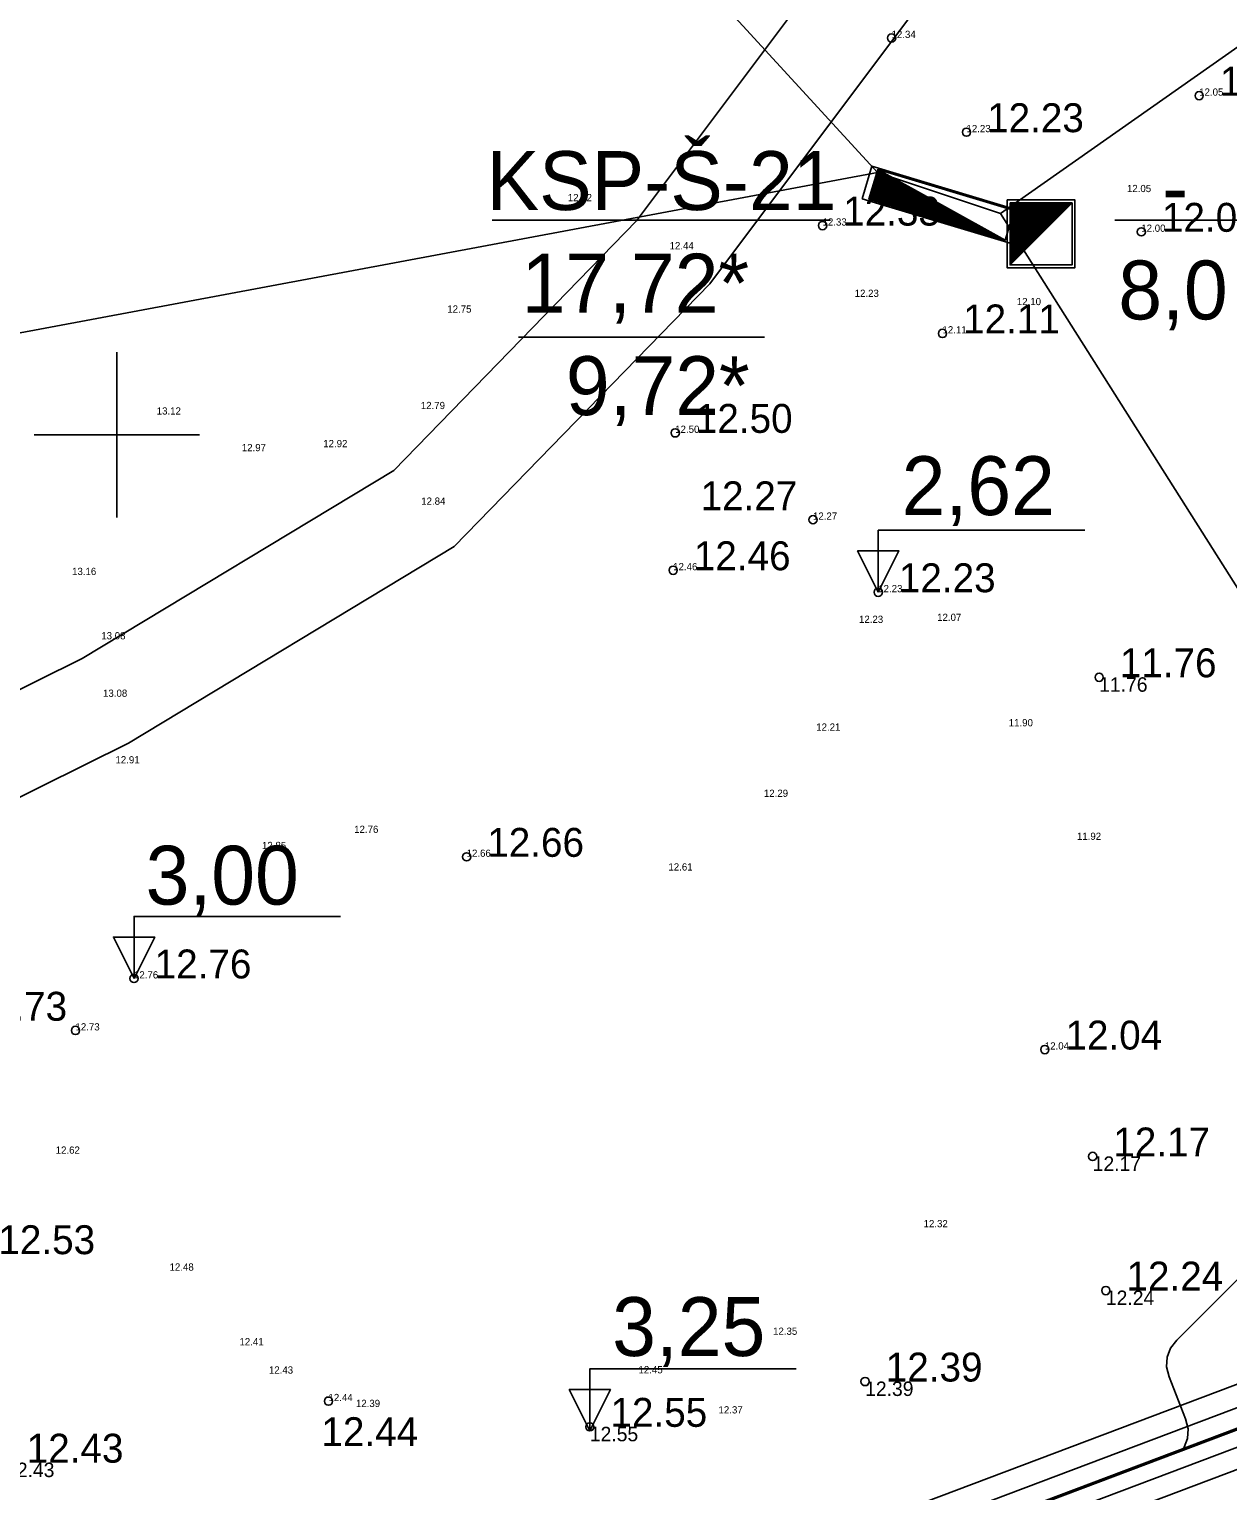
# Model space of a CAD drawing. Extents: x 433497 to 434382, y 6534486 to 6534993.
# Drawn here: x 433695.8 to 433753.8, y 6534648.9 to 6534719.6 of the extents above; entities that cross this region are included whole.
import ezdxf

# ---------------------------------------------------------------- set-up
doc = ezdxf.new("R2010")
doc.units = 0
for name, color, linetype in [('Default', 7, 'Continuous'), ('GEOLPUNKT', 7, 'Continuous'), ('jääkpaksus', 7, 'Continuous'), ('kataster', 7, 'Continuous'), ('KORGUS-EH2000', 7, 'Continuous'), ('l__x00e4__bil__x00f5__iked', 7, 'Continuous'), ('Lamami horisontaal', 7, 'Continuous'), ('MOOTKORG-EH2000', 7, 'Continuous'), ('PIIR', 7, 'Continuous'), ('TEE', 7, 'Continuous'), ('VORK', 7, 'Continuous')]:
    doc.layers.add(name, color=color, linetype=linetype)

msp = doc.modelspace()

# ---------------------------------------------------------------- linework, layer by layer
at = {"layer": 'Default'}
msp.add_lwpolyline([(433617.12, 6534791.025), (433632.75, 6534606.045), (434137.38, 6534796.515), (434127.69, 6534855.6), (433968.21, 6534911.925), (433942.38, 6534904.035), (433920.99, 6534907.275)], close=True, dxfattribs=at)
msp.add_lwpolyline([(433617.12, 6534791.025), (433632.75, 6534606.045), (434137.38, 6534796.515), (434127.69, 6534855.6), (433968.21, 6534911.925), (433942.38, 6534904.035), (433920.99, 6534907.275)], close=True, dxfattribs=at)
msp.add_lwpolyline([(433617.12, 6534791.025), (433632.75, 6534606.045), (434137.38, 6534796.515), (434127.69, 6534855.6), (433968.21, 6534911.925), (433942.38, 6534904.035), (433920.99, 6534907.275)], close=True, dxfattribs=at)
at = {"layer": 'GEOLPUNKT'}
for p, q in [((433742.498, 6534709.584), (433736.822, 6534712.731)), ((433742.654, 6534709.537), (433736.832, 6534712.765)), ((433742.809, 6534709.491), (433736.842, 6534712.799)), ((433742.965, 6534709.444), (433736.852, 6534712.833)), ((433743.032, 6534709.424), (433736.857, 6534712.847)), ((433739.227, 6534710.568), (433736.608, 6534712.02)), ((433739.383, 6534710.521), (433736.618, 6534712.054)), ((433739.539, 6534710.474), (433736.628, 6534712.088)), ((433739.695, 6534710.427), (433736.639, 6534712.122)), ((433739.85, 6534710.381), (433736.649, 6534712.156)), ((433740.006, 6534710.334), (433736.659, 6534712.19)), ((433740.162, 6534710.287), (433736.669, 6534712.223)), ((433740.318, 6534710.24), (433736.679, 6534712.257)), ((433740.473, 6534710.193), (433736.69, 6534712.291)), ((433740.629, 6534710.146), (433736.7, 6534712.325)), ((433740.785, 6534710.1), (433736.71, 6534712.359)), ((433740.941, 6534710.053), (433736.72, 6534712.393)), ((433741.096, 6534710.006), (433736.73, 6534712.427)), ((433741.252, 6534709.959), (433736.74, 6534712.46)), ((433741.408, 6534709.912), (433736.751, 6534712.494)), ((433741.564, 6534709.865), (433736.761, 6534712.528)), ((433741.719, 6534709.818), (433736.771, 6534712.562)), ((433741.875, 6534709.772), (433736.781, 6534712.596)), ((433742.031, 6534709.725), (433736.791, 6534712.63)), ((433742.187, 6534709.678), (433736.802, 6534712.664)), ((433742.342, 6534709.631), (433736.812, 6534712.697)), ((433736.58, 6534711.364), (433736.435, 6534711.445)), ((433736.736, 6534711.318), (433736.445, 6534711.479)), ((433736.891, 6534711.271), (433736.455, 6534711.512)), ((433737.047, 6534711.224), (433736.465, 6534711.546)), ((433737.203, 6534711.177), (433736.476, 6534711.58)), ((433737.359, 6534711.13), (433736.486, 6534711.614)), ((433737.514, 6534711.083), (433736.496, 6534711.648)), ((433737.67, 6534711.036), (433736.506, 6534711.682)), ((433737.826, 6534710.99), (433736.516, 6534711.716)), ((433737.982, 6534710.943), (433736.527, 6534711.749)), ((433738.137, 6534710.896), (433736.537, 6534711.783)), ((433738.293, 6534710.849), (433736.547, 6534711.817)), ((433738.449, 6534710.802), (433736.557, 6534711.851)), ((433738.604, 6534710.755), (433736.567, 6534711.885)), ((433738.76, 6534710.709), (433736.577, 6534711.919)), ((433738.916, 6534710.662), (433736.588, 6534711.953)), ((433739.072, 6534710.615), (433736.598, 6534711.986)), ((433743.262, 6534708.233), (433746.262, 6534711.233)), ((433743.262, 6534708.263), (433746.232, 6534711.233)), ((433743.262, 6534708.334), (433746.161, 6534711.233)), ((433743.262, 6534708.405), (433746.09, 6534711.233)), ((433743.262, 6534708.476), (433746.02, 6534711.233)), ((433743.262, 6534708.546), (433745.949, 6534711.233)), ((433743.262, 6534708.617), (433745.878, 6534711.233)), ((433743.262, 6534708.688), (433745.807, 6534711.233)), ((433743.262, 6534708.758), (433745.737, 6534711.233)), ((433743.262, 6534708.829), (433745.666, 6534711.233)), ((433743.262, 6534708.9), (433745.595, 6534711.233)), ((433743.262, 6534708.971), (433745.525, 6534711.233)), ((433743.262, 6534709.041), (433745.454, 6534711.233)), ((433743.262, 6534709.112), (433745.383, 6534711.233)), ((433743.262, 6534709.183), (433745.313, 6534711.233)), ((433743.262, 6534709.253), (433745.242, 6534711.233)), ((433743.262, 6534709.324), (433745.171, 6534711.233)), ((433743.262, 6534709.395), (433745.1, 6534711.233)), ((433743.262, 6534709.465), (433745.03, 6534711.233)), ((433743.262, 6534709.536), (433744.959, 6534711.233)), ((433743.262, 6534709.607), (433744.888, 6534711.233)), ((433743.262, 6534709.678), (433744.818, 6534711.233)), ((433743.262, 6534709.748), (433744.747, 6534711.233)), ((433743.262, 6534709.819), (433744.676, 6534711.233)), ((433743.262, 6534709.89), (433744.605, 6534711.233)), ((433743.262, 6534709.96), (433744.535, 6534711.233)), ((433743.262, 6534710.031), (433744.464, 6534711.233)), ((433743.262, 6534710.102), (433744.393, 6534711.233)), ((433743.262, 6534710.173), (433744.323, 6534711.233)), ((433743.262, 6534710.243), (433744.252, 6534711.233)), ((433743.262, 6534710.314), (433744.181, 6534711.233)), ((433743.262, 6534710.385), (433744.11, 6534711.233)), ((433743.262, 6534710.455), (433744.04, 6534711.233)), ((433743.262, 6534710.526), (433743.969, 6534711.233)), ((433743.262, 6534710.597), (433743.898, 6534711.233)), ((433743.262, 6534710.668), (433743.828, 6534711.233)), ((433743.262, 6534710.738), (433743.757, 6534711.233)), ((433743.262, 6534710.809), (433743.686, 6534711.233)), ((433743.262, 6534710.88), (433743.615, 6534711.233)), ((433743.262, 6534710.95), (433743.545, 6534711.233)), ((433743.262, 6534711.021), (433743.474, 6534711.233)), ((433743.262, 6534711.092), (433743.403, 6534711.233)), ((433743.262, 6534711.163), (433743.333, 6534711.233)), ((433744.762, 6534709.733), (433744.762, 6534709.733))]:
    msp.add_line(p, q, dxfattribs=at)
for points in [[(433736.094, 6534711.437), (433736.567, 6534713.008), (433743.795, 6534710.834), (433743.323, 6534709.263)], [(433736.425, 6534711.411), (433736.857, 6534712.847), (433743.464, 6534710.86), (433743.032, 6534709.424)], [(433743.121, 6534711.374), (433746.403, 6534711.374), (433746.403, 6534708.092), (433743.121, 6534708.092)], [(433743.262, 6534711.233), (433746.262, 6534711.233), (433746.262, 6534708.233), (433743.262, 6534708.233)]]:
    msp.add_lwpolyline(points, close=True, dxfattribs=at)
for points in [[(433718.185, 6534710.392), (433734.57, 6534710.392)], [(433748.334, 6534710.392), (433754.462, 6534710.392)], [(433719.456, 6534704.738), (433731.372, 6534704.738)]]:
    msp.add_lwpolyline(points, dxfattribs=at)
at = {"layer": 'jääkpaksus'}
for points in [[(433736.877, 6534692.381), (433736.877, 6534695.381), (433746.877, 6534695.381)], [(433700.832, 6534673.681), (433700.832, 6534676.681), (433710.832, 6534676.681)], [(433722.908, 6534651.771), (433722.908, 6534654.771), (433732.908, 6534654.771)]]:
    msp.add_lwpolyline(points, dxfattribs=at)
for points in [[(433736.877, 6534692.381), (433735.877, 6534694.381), (433737.877, 6534694.381)], [(433700.832, 6534673.681), (433699.832, 6534675.681), (433701.832, 6534675.681)], [(433722.908, 6534651.771), (433721.908, 6534653.771), (433723.908, 6534653.771)]]:
    msp.add_lwpolyline(points, close=True, dxfattribs=at)
at = {"layer": 'kataster'}
msp.add_lwpolyline([(433617.102, 6534791.002), (433632.769, 6534606.029), (434137.446, 6534796.469), (434127.827, 6534855.589), (433950.026, 6534918.39)], close=True, dxfattribs=at)
at = {"layer": 'KORGUS-EH2000'}
for centre in [(433737.522, 6534719.218), (433752.422, 6534716.424), (433741.151, 6534714.657), (433734.18, 6534710.135), (433749.618, 6534709.833), (433739.989, 6534704.913), (433727.044, 6534700.098), (433733.718, 6534695.893), (433726.946, 6534693.446), (433736.877, 6534692.381), (433747.578, 6534688.263), (433716.941, 6534679.57), (433700.832, 6534673.681), (433697.997, 6534671.163), (433744.945, 6534670.239), (433747.263, 6534665.062), (433747.902, 6534658.569), (433736.242, 6534654.164), (433710.252, 6534653.215), (433722.908, 6534651.971)]:
    msp.add_circle(centre, 0.2, dxfattribs=at)
at = {"layer": 'l__x00e4__bil__x00f5__iked'}
for points in [[(433620.07, 6534691.039), (433627.105, 6534692.187), (433736.834, 6534712.709), (433742.792, 6534710.723), (433822.234, 6534766.498), (433986.579, 6534812.177), (434120.472, 6534848.091), (434132.163, 6534850.175)], [(433633.89, 6534824.093), (433654.744, 6534802.081), (433736.834, 6534712.709), (433742.792, 6534710.723), (433773.907, 6534661.568), (433785.989, 6534638.563)]]:
    msp.add_lwpolyline(points, dxfattribs=at)
at = {"layer": 'Lamami horisontaal'}
msp.add_lwpolyline([(433751.537, 6534650.808), (433751.689, 6534650.989), (433751.864, 6534651.411), (433751.889, 6534651.867), (433751.765, 6534652.358), (433750.971, 6534654.387), (433750.846, 6534654.88), (433750.866, 6534655.341), (433751.032, 6534655.772), (433751.344, 6534656.173), (433763.457, 6534668.298)], dxfattribs=at)
at = {"layer": 'PIIR'}
for points in [[(433632.021, 6534604.835), (434138.248, 6534795.936), (434128.468, 6534856.135), (433968.226, 6534912.818), (433942.33, 6534904.85), (433920.952, 6534908.165), (433616.327, 6534791.524), (433632.021, 6534604.835)], [(433632.732, 6534605.959), (434137.353, 6534796.454), (434127.754, 6534855.539), (433968.208, 6534911.976), (433942.39, 6534904.031), (433921.04, 6534907.341), (433617.174, 6534790.992), (433632.732, 6534605.959)], [(433633.446, 6534604.304), (434134.891, 6534793.6)]]:
    msp.add_lwpolyline(points, dxfattribs=at)
for points in [[(433618.234, 6534790.327), (433921.149, 6534906.313), (433942.464, 6534903.008), (433968.187, 6534910.923), (434126.862, 6534854.794), (434136.235, 6534797.101), (433633.617, 6534607.362)], [(433619.24, 6534789.695), (433634.52, 6534608.851), (434135.141, 6534797.808), (434125.908, 6534854.108), (433968.165, 6534909.82), (433942.53, 6534901.99), (433921.212, 6534905.219)], [(433619.24, 6534789.695), (433634.52, 6534608.851), (434135.141, 6534797.808), (434125.908, 6534854.108), (433968.165, 6534909.82), (433942.53, 6534901.99), (433921.212, 6534905.219)]]:
    msp.add_lwpolyline(points, close=True, dxfattribs=at)
at = {"layer": 'TEE'}
for points in [[(433629.62, 6534620.933), (433635.717, 6534625.88), (433648.001, 6534643.205), (433657.255, 6534659.779), (433669.771, 6534672.932), (433683.244, 6534681.694), (433698.319, 6534689.166), (433713.422, 6534698.28), (433725.167, 6534710.357), (433749.242, 6534742.46), (433772.059, 6534766.624), (433790.138, 6534781.288), (433800.698, 6534786.54), (433824.398, 6534799.304), (433830.425, 6534802.129), (433845.699, 6534809.155)], [(433604.844, 6534600.897), (433614.152, 6534605.53), (433628.909, 6534614.355), (433639.149, 6534622.663), (433651.948, 6534640.714), (433661.037, 6534656.993), (433672.77, 6534669.323), (433685.557, 6534677.639), (433700.561, 6534685.076), (433716.344, 6534694.6), (433728.716, 6534707.321), (433752.812, 6534739.453), (433775.036, 6534762.988), (433798.049, 6534780.902), (433815.08, 6534789.81), (433832.403, 6534797.909), (433848.041, 6534804.286)]]:
    msp.add_lwpolyline(points, dxfattribs=at)
at = {"layer": 'VORK'}
for p, q in [((433700, 6534704), (433700, 6534696)), ((433696, 6534700), (433704, 6534700))]:
    msp.add_line(p, q, dxfattribs=at)

# ---------------------------------------------------------------- texts
at = {"layer": 'GEOLPUNKT'}
for s, p in [('KSP-Š-21', (433717.911, 6534710.888)), ('-', (433750.624, 6534710.557)), ('17,72*', (433719.603, 6534705.923)), ('8,0', (433748.505, 6534705.592)), ('9,72*', (433721.748, 6534700.958))]:
    msp.add_text(s, height=2.85, dxfattribs=at).set_placement(p)
at = {"layer": 'jääkpaksus'}
for s, p in [('2,62', (433738.013, 6534696.116)), ('3,00', (433701.395, 6534677.256)), ('3,25', (433723.99, 6534655.399))]:
    msp.add_text(s, height=2.85, rotation=360, dxfattribs=at).set_placement(p)
at = {"layer": 'KORGUS-EH2000'}
for s, p in [('12.05', (433753.422, 6534716.424)), ('12.23', (433742.151, 6534714.657)), ('12.33', (433735.18, 6534710.135)), ('12.00', (433750.618, 6534709.833)), ('12.11', (433740.989, 6534704.913)), ('12.50', (433728.044, 6534700.098)), ('12.27', (433728.272, 6534696.35)), ('12.46', (433727.946, 6534693.446)), ('12.23', (433737.877, 6534692.381)), ('11.76', (433748.578, 6534688.263)), ('12.66', (433717.941, 6534679.57)), ('12.76', (433701.832, 6534673.681)), ('12.73', (433692.904, 6534671.633)), ('12.04', (433745.945, 6534670.239)), ('12.17', (433748.263, 6534665.062)), ('12.53', (433694.262, 6534660.331)), ('12.24', (433748.902, 6534658.569)), ('12.39', (433737.242, 6534654.164)), ('12.55', (433723.908, 6534651.971)), ('12.44', (433709.908, 6534651.035)), ('12.43', (433695.635, 6534650.236))]:
    msp.add_text(s, height=1.4, dxfattribs=at).set_placement(p)
at = {"layer": 'MOOTKORG-EH2000'}
for s, height, p in [('12.34', 0.35, (433737.522, 6534719.218)), ('12.05', 0.35, (433752.422, 6534716.424)), ('12.23', 0.35, (433741.151, 6534714.657)), ('12.05', 0.35, (433748.924, 6534711.755)), ('12.62', 0.35, (433721.841, 6534711.316)), ('12.33', 0.35, (433734.18, 6534710.135)), ('12.00', 0.35, (433749.618, 6534709.833)), ('12.44', 0.35, (433726.771, 6534708.985)), ('12.23', 0.35, (433735.735, 6534706.681)), ('12.10', 0.35, (433743.59, 6534706.281)), ('12.75', 0.35, (433716.005, 6534705.919)), ('12.11', 0.35, (433739.989, 6534704.913)), ('12.79', 0.35, (433714.722, 6534701.249)), ('13.12', 0.35, (433701.931, 6534700.984)), ('12.50', 0.35, (433727.044, 6534700.098)), ('12.97', 0.35, (433706.052, 6534699.211)), ('12.92', 0.35, (433709.996, 6534699.405)), ('12.84', 0.35, (433714.742, 6534696.617)), ('12.27', 0.35, (433733.718, 6534695.893)), ('12.46', 0.35, (433726.946, 6534693.446)), ('13.16', 0.35, (433697.832, 6534693.216)), ('12.23', 0.35, (433736.877, 6534692.381)), ('12.23', 0.35, (433735.946, 6534690.896)), ('12.07', 0.35, (433739.73, 6534690.991)), ('13.08', 0.35, (433699.247, 6534690.1)), ('11.76', 0.7, (433747.578, 6534687.563)), ('13.08', 0.35, (433699.332, 6534687.318)), ('12.21', 0.35, (433733.874, 6534685.677)), ('11.90', 0.35, (433743.197, 6534685.89)), ('12.91', 0.35, (433699.933, 6534684.094)), ('12.29', 0.35, (433731.339, 6534682.472)), ('12.76', 0.35, (433711.495, 6534680.727)), ('12.85', 0.35, (433707.031, 6534679.945)), ('11.92', 0.35, (433746.501, 6534680.39)), ('12.66', 0.35, (433716.941, 6534679.57)), ('12.61', 0.35, (433726.715, 6534678.907)), ('12.76', 0.35, (433700.832, 6534673.681)), ('12.76', 0.35, (433700.832, 6534673.681)), ('12.73', 0.35, (433697.997, 6534671.163)), ('12.04', 0.35, (433744.945, 6534670.239)), ('12.62', 0.35, (433697.038, 6534665.195)), ('12.17', 0.7, (433747.263, 6534664.362)), ('12.32', 0.35, (433739.074, 6534661.633)), ('12.48', 0.35, (433702.553, 6534659.534)), ('12.24', 0.7, (433747.902, 6534657.869)), ('12.41', 0.35, (433705.939, 6534655.916)), ('12.35', 0.35, (433731.784, 6534656.427)), ('12.43', 0.35, (433707.365, 6534654.547)), ('12.45', 0.35, (433725.266, 6534654.561)), ('12.39', 0.7, (433736.242, 6534653.464)), ('12.44', 0.35, (433710.252, 6534653.215)), ('12.39', 0.35, (433711.579, 6534652.929)), ('12.37', 0.35, (433729.142, 6534652.618)), ('12.37', 0.35, (433729.142, 6534652.618)), ('12.55', 0.7, (433722.908, 6534651.271)), ('12.43', 0.7, (433694.635, 6534649.536))]:
    msp.add_text(s, height=height, dxfattribs=at).set_placement(p)

doc.saveas('drawing.dxf')
